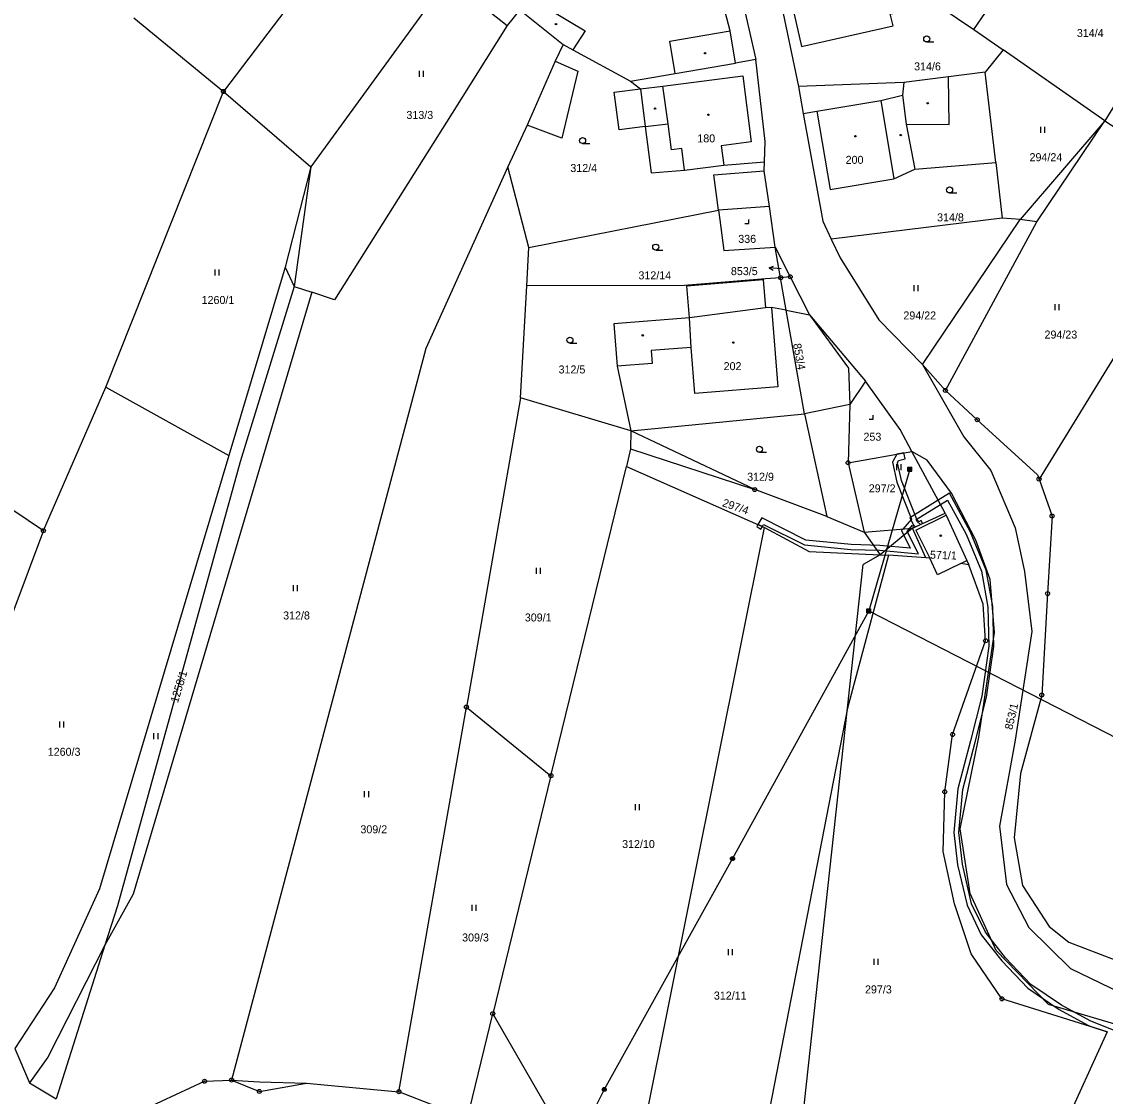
# Model space of a CAD drawing. Extents: x -745926 to -742978, y -968282 to -965689.
# Drawn here: x -745276.5 to -745141.1, y -967171.8 to -967037.5 of the extents above; entities that cross this region are included whole.
import ezdxf

# ---------------------------------------------------------------- set-up
doc = ezdxf.new("R2010")
doc.units = 0
for name, color, linetype in [('Hranice parcel', 7, 'Continuous'), ('Parcelní čísla', 7, 'Continuous'), ('Pop  PČ popisy', 7, 'Continuous'), ('Poz předměty', 7, 'Continuous'), ('Vnitřní kresba', 7, 'Continuous'), ('Věcná břemena k části', 7, 'Continuous'), ('Značky bodu BP', 7, 'Continuous'), ('Značky budov', 7, 'Continuous'), ('Značky kultur', 7, 'Continuous')]:
    doc.layers.add(name, color=color, linetype=linetype)

msp = doc.modelspace()

# ---------------------------------------------------------------- linework, layer by layer
at = {"layer": 'Hranice parcel'}
for p, q in [((-745131.16, -967033.55), (-745141.13, -967049.86)), ((-745161.57, -967035.67), (-745157.47, -967038.45)), ((-745262.49, -967036.98), (-745251.29, -967046.18)), ((-745214.25, -967035.97), (-745208.81, -967040.3)), ((-745157.47, -967038.45), (-745153.8, -967040.96)), ((-745153.8, -967040.96), (-745156.06, -967043.77)), ((-745141.13, -967049.86), (-745153.8, -967040.96)), ((-745184.74, -967042.18), (-745187.27, -967042.62)), ((-745154.74, -967055.05), (-745156.06, -967043.77)), ((-745265.99, -967083.14), (-745251.29, -967046.18)), ((-745251.29, -967046.18), (-745240.35, -967055.61)), ((-745179.42, -967045.57), (-745178.81, -967048.94)), ((-745141.13, -967049.86), (-745151.7, -967062.16)), ((-745240.35, -967055.61), (-745243.55, -967068.15)), ((-745213.09, -967065.69), (-745215.73, -967055.61)), ((-745154.74, -967055.05), (-745153.93, -967062.02)), ((-745213.09, -967065.69), (-745189.4, -967061.03)), ((-745183.02, -967060.56), (-745189.4, -967061.03)), ((-745182.31, -967065.65), (-745183.02, -967060.56)), ((-745153.93, -967062.02), (-745175.32, -967064.62)), ((-745163.92, -967080.29), (-745151.7, -967062.16)), ((-745151.7, -967062.16), (-745153.93, -967062.02)), ((-745130.76, -967064.38), (-745149.34, -967094.62)), ((-745213.36, -967070.48), (-745213.09, -967065.69)), ((-745182.31, -967065.65), (-745180.44, -967069.34)), ((-745181.64, -967069.45), (-745182.31, -967065.65)), ((-745243.55, -967068.15), (-745250.59, -967091.69)), ((-745180.44, -967069.34), (-745181.64, -967069.45)), ((-745180.93, -967073.53), (-745181.64, -967069.45)), ((-745214.13, -967084.45), (-745213.36, -967070.48)), ((-745317.4, -967071.42), (-745273.79, -967101.07)), ((-745178.66, -967086.47), (-745180.93, -967073.53)), ((-745273.79, -967101.07), (-745265.99, -967083.14)), ((-745265.99, -967083.14), (-745250.59, -967091.69)), ((-745171.03, -967082.4), (-745173, -967085.3)), ((-745214.13, -967084.45), (-745220.91, -967123.12)), ((-745200.36, -967088.61), (-745214.13, -967084.45)), ((-745173, -967085.3), (-745178.66, -967086.47)), ((-745173, -967085.3), (-745173.2, -967092.59)), ((-745200.36, -967088.61), (-745178.66, -967086.47)), ((-745178.66, -967086.47), (-745175.87, -967099.31)), ((-745173.2, -967092.59), (-745165.25, -967091.18)), ((-745161.08, -967098.89), (-745165.25, -967091.18)), ((-745210.34, -967131.7), (-745200.89, -967093.07)), ((-745200.89, -967093.07), (-745183.65, -967100.66)), ((-745175.87, -967099.31), (-745171.18, -967101.25)), ((-745165.17, -967100.77), (-745161.08, -967098.89)), ((-745202.34, -967193.92), (-745183.65, -967100.66)), ((-745171.18, -967101.25), (-745165.17, -967100.77)), ((-745163.47, -967104.47), (-745165.17, -967100.77)), ((-745273.79, -967101.07), (-745289.83, -967143.94)), ((-745163.47, -967104.47), (-745168.16, -967104.13)), ((-745158.35, -967104.82), (-745158.1, -967105.36)), ((-745229.35, -967171.2), (-745220.91, -967123.12)), ((-745220.91, -967123.12), (-745210.34, -967131.7)), ((-745210.34, -967131.7), (-745217.61, -967161.45)), ((-745266.1, -967152.9), (-745273.25, -967166.88)), ((-745221.16, -967175.97), (-745217.61, -967161.45)), ((-745277.35, -967165.81), (-745275.54, -967170.09)), ((-745273.25, -967166.88), (-745275.54, -967170.09)), ((-745275.54, -967170.09), (-745272.2, -967172.1))]:
    msp.add_line(p, q, dxfattribs=at)
for points in [[(-745221.16, -967004.14), (-745225.97, -967012.23), (-745227.76, -967015.24), (-745251.29, -967046.18)], [(-745157.47, -967038.45), (-745155.56, -967035.64), (-745148.37, -967021.19), (-745150.01, -967017.97)], [(-745213.9, -967019.17), (-745216.8, -967023.23), (-745240.35, -967055.61)], [(-745189.08, -967024.61), (-745186.49, -967034.46), (-745184.74, -967042.18)], [(-745187.27, -967042.62), (-745187.96, -967038.61), (-745188.97, -967034.61), (-745190.87, -967026.9)], [(-745182.66, -967029.42), (-745181.59, -967029.18), (-745181.27, -967030.59), (-745179.03, -967040.55), (-745167.58, -967037.97), (-745167.93, -967036.46), (-745161.57, -967035.67)], [(-745182.66, -967029.42), (-745181.69, -967034.61), (-745179.42, -967045.57)], [(-745214.25, -967035.97), (-745215.81, -967037.95), (-745222.69, -967048.89), (-745237.4, -967072.23), (-745240.22, -967071.25)], [(-745208.81, -967040.3), (-745209.8, -967042.4), (-745213.3, -967050.4), (-745215.73, -967055.61)], [(-745208.81, -967040.3), (-745207.59, -967040.96), (-745200.38, -967044.87)], [(-745183.65, -967054.95), (-745183.55, -967052.43), (-745184.74, -967042.18)], [(-745200.38, -967044.87), (-745194.81, -967043.91), (-745187.27, -967042.62)], [(-745156.06, -967043.77), (-745160.67, -967044.36), (-745166.24, -967045.05), (-745179.42, -967045.57)], [(-745200.38, -967044.87), (-745199.17, -967045.86), (-745198.57, -967050.57), (-745197.83, -967056.36), (-745193.65, -967056.02), (-745188.75, -967055.38), (-745183.65, -967054.95)], [(-745178.81, -967048.94), (-745177.11, -967048.64), (-745175.46, -967058.44), (-745167.48, -967057.1), (-745164.85, -967055.87), (-745154.74, -967055.05)], [(-745178.81, -967048.94), (-745176.36, -967062.39), (-745175.32, -967064.62)], [(-745141.13, -967049.86), (-745131.6, -967056), (-745130.2, -967056.6), (-745127.59, -967058.73)], [(-745215.73, -967055.61), (-745226, -967078.32), (-745250.27, -967169.74)], [(-745183.02, -967060.56), (-745183.7, -967056.11), (-745183.65, -967054.95)], [(-745189.4, -967061.03), (-745189.24, -967062.22), (-745188.74, -967066.04), (-745182.31, -967065.65)], [(-745175.32, -967064.62), (-745174.21, -967066.97), (-745169.34, -967074.73), (-745163.92, -967080.29)], [(-745243.55, -967068.15), (-745242.42, -967070.54), (-745240.22, -967071.25)], [(-745181.64, -967069.45), (-745183.53, -967069.59), (-745193.67, -967070.41), (-745213.36, -967070.48)], [(-745180.44, -967069.34), (-745178.03, -967074.1), (-745171.03, -967082.4)], [(-745240.22, -967071.25), (-745262.57, -967146.49), (-745266.1, -967152.9)], [(-745180.93, -967073.53), (-745182.77, -967073.17), (-745183.52, -967073.23), (-745193.04, -967074.45), (-745202.5, -967075.21), (-745202.07, -967080.53), (-745200.36, -967088.61)], [(-745163.92, -967080.29), (-745161.04, -967083.55), (-745157.06, -967087.21), (-745149.52, -967094.1), (-745149.34, -967094.62)], [(-745165.25, -967091.18), (-745166.68, -967088.44), (-745171.03, -967082.4)], [(-745200.36, -967088.61), (-745200.39, -967090.85), (-745200.89, -967093.07)], [(-745175.87, -967099.31), (-745184.88, -967095.93), (-745200.36, -967088.61)], [(-745250.59, -967091.69), (-745266.78, -967145.82), (-745272.38, -967158.2), (-745277.35, -967165.81)], [(-745149.34, -967094.62), (-745147.71, -967099.24), (-745148.26, -967108.93), (-745148.99, -967121.62), (-745151.66, -967131.42), (-745152.45, -967139.46), (-745151.39, -967145.42), (-745148.07, -967150.56), (-745145.63, -967152.52), (-745139.72, -967154.74)], [(-745161.08, -967098.89), (-745160.96, -967099.14), (-745158.35, -967104.82)], [(-745183.65, -967100.66), (-745178.07, -967103.66), (-745169.2, -967104.1), (-745168.16, -967104.13)], [(-745168.16, -967104.13), (-745173.28, -967123.27), (-745188.63, -967202.08)], [(-745158.1, -967105.36), (-745159.1, -967105.18), (-745162.03, -967106.6), (-745163, -967104.5), (-745163.47, -967104.47)], [(-745140.8, -967163.7), (-745153.98, -967159.59), (-745157.83, -967153.98), (-745159.91, -967147.72), (-745161.3, -967141.18), (-745161.12, -967133.71), (-745160.15, -967126.55), (-745156.01, -967114.84), (-745156.32, -967110.25), (-745158.1, -967105.36)], [(-745217.61, -967161.45), (-745208.73, -967176.85), (-745209.67, -967186.88)], [(-745140.8, -967163.7), (-745146.38, -967175.86), (-745148.19, -967179.8), (-745158.64, -967202.56)], [(-745263.16, -967178.41), (-745260.83, -967173.2), (-745253.64, -967169.89), (-745250.27, -967169.74)], [(-745250.27, -967169.74), (-745246.79, -967171.17), (-745240.91, -967170.14), (-745229.35, -967171.2)], [(-745221.16, -967175.97), (-745224.66, -967173.06), (-745229.35, -967171.2)]]:
    msp.add_lwpolyline(points, dxfattribs=at)
at = {"layer": 'Pop  PČ popisy'}
for p, q in [((-745183.06, -967068.23), (-745182.54, -967068.01)), ((-745181.56, -967068.33), (-745183.06, -967068.23)), ((-745183.06, -967068.23), (-745182.58, -967068.51))]:
    msp.add_line(p, q, dxfattribs=at)
at = {"layer": 'Poz předměty'}
for p, q in [((-745165.47, -967093.4), (-745170.61, -967111.1)), ((-745165.72, -967093.15), (-745165.22, -967093.15)), ((-745165.72, -967093.65), (-745165.72, -967093.15)), ((-745165.72, -967093.25), (-745165.22, -967093.25)), ((-745165.72, -967093.35), (-745165.22, -967093.35)), ((-745165.72, -967093.45), (-745165.22, -967093.45)), ((-745165.72, -967093.55), (-745165.22, -967093.55)), ((-745165.72, -967093.65), (-745165.22, -967093.65)), ((-745165.62, -967093.65), (-745165.62, -967093.15)), ((-745165.52, -967093.65), (-745165.52, -967093.15)), ((-745165.42, -967093.65), (-745165.42, -967093.15)), ((-745165.32, -967093.65), (-745165.32, -967093.15)), ((-745165.22, -967093.65), (-745165.22, -967093.15)), ((-745170.61, -967111.1), (-745187.65, -967142.06)), ((-745170.86, -967110.85), (-745170.36, -967110.85)), ((-745170.86, -967111.35), (-745170.86, -967110.85)), ((-745170.86, -967110.95), (-745170.36, -967110.95)), ((-745170.86, -967111.05), (-745170.36, -967111.05)), ((-745170.86, -967111.15), (-745170.36, -967111.15)), ((-745170.86, -967111.25), (-745170.36, -967111.25)), ((-745170.86, -967111.35), (-745170.36, -967111.35)), ((-745170.76, -967111.35), (-745170.76, -967110.85)), ((-745170.66, -967111.35), (-745170.66, -967110.85)), ((-745170.61, -967111.1), (-745093.52, -967150.64)), ((-745170.56, -967111.35), (-745170.56, -967110.85)), ((-745170.46, -967111.35), (-745170.46, -967110.85)), ((-745170.36, -967111.35), (-745170.36, -967110.85)), ((-745187.65, -967142.06), (-745203.68, -967170.92)), ((-745203.68, -967170.92), (-745225.94, -967214.52))]:
    msp.add_line(p, q, dxfattribs=at)
for centre, radius in [((-745187.65, -967142.06), 0.25), ((-745187.65, -967142.06), 0.2), ((-745187.65, -967142.06), 0.15), ((-745187.65, -967142.06), 0.1), ((-745187.65, -967142.06), 0.05), ((-745203.68, -967170.92), 0.25), ((-745203.68, -967170.92), 0.2), ((-745203.68, -967170.92), 0.15), ((-745203.68, -967170.92), 0.1), ((-745203.68, -967170.92), 0.05)]:
    msp.add_circle(centre, radius, dxfattribs=at)
at = {"layer": 'Vnitřní kresba'}
for p, q in [((-745213, -967034.43), (-745206.07, -967038.58)), ((-745218.56, -967035.78), (-745215.81, -967037.95)), ((-745206.07, -967038.58), (-745207.59, -967040.96)), ((-745195.5, -967039.89), (-745187.96, -967038.61)), ((-745194.81, -967043.91), (-745195.5, -967039.89)), ((-745209.8, -967042.4), (-745207, -967043.65)), ((-745207, -967043.65), (-745209, -967052)), ((-745196.34, -967045.5), (-745186.38, -967044.2)), ((-745186.38, -967044.2), (-745185.3, -967052.48)), ((-745166.24, -967045.05), (-745166.42, -967046.64)), ((-745160.56, -967050.3), (-745160.67, -967044.36)), ((-745202.43, -967046.28), (-745199.17, -967045.86)), ((-745201.81, -967050.99), (-745202.43, -967046.28)), ((-745199.17, -967045.86), (-745196.34, -967045.5)), ((-745195.7, -967050.2), (-745196.34, -967045.5)), ((-745177.11, -967048.64), (-745169.13, -967047.3)), ((-745169.13, -967047.3), (-745166.42, -967046.64)), ((-745169.13, -967047.3), (-745167.48, -967057.1)), ((-745166.42, -967046.64), (-745165.93, -967050.27)), ((-745209, -967052), (-745213.3, -967050.4)), ((-745198.57, -967050.57), (-745201.81, -967050.99)), ((-745198.57, -967050.57), (-745195.7, -967050.2)), ((-745195.28, -967053.48), (-745195.7, -967050.2)), ((-745165.93, -967050.27), (-745164.85, -967055.87)), ((-745165.93, -967050.27), (-745160.56, -967050.3)), ((-745149.63, -967062.45), (-745141.13, -967049.86)), ((-745194, -967053.31), (-745195.28, -967053.48)), ((-745193.65, -967056.02), (-745194, -967053.31)), ((-745185.3, -967052.48), (-745189.06, -967052.97)), ((-745189.06, -967052.97), (-745188.75, -967055.38)), ((-745240.35, -967055.61), (-745242.42, -967070.54)), ((-745189.98, -967056.59), (-745183.7, -967056.11)), ((-745189.4, -967061.03), (-745189.98, -967056.59)), ((-745161.04, -967083.55), (-745149.63, -967062.45)), ((-745149.63, -967062.45), (-745151.7, -967062.16)), ((-745242.42, -967070.54), (-745249.19, -967092.46)), ((-745193.36, -967070.46), (-745183.81, -967069.69)), ((-745193.04, -967074.45), (-745193.36, -967070.46)), ((-745183.81, -967069.69), (-745183.52, -967073.23)), ((-745182.77, -967073.17), (-745181.98, -967083.11)), ((-745180.93, -967073.53), (-745178.03, -967074.1)), ((-745192.82, -967078.16), (-745193.04, -967074.45)), ((-745178.03, -967074.1), (-745173.16, -967080.74)), ((-745192.82, -967078.16), (-745197.83, -967078.56)), ((-745197.83, -967078.56), (-745197.7, -967080.18)), ((-745192.36, -967083.94), (-745192.82, -967078.16)), ((-745197.7, -967080.18), (-745202.07, -967080.53)), ((-745163.92, -967080.29), (-745158.72, -967089.35)), ((-745173.16, -967080.74), (-745173, -967085.3)), ((-745181.98, -967083.11), (-745192.36, -967083.94)), ((-745158.72, -967089.35), (-745155.38, -967093.57)), ((-745200.39, -967090.85), (-745184.88, -967095.93)), ((-745163.32, -967092.26), (-745165.25, -967091.18)), ((-745249.19, -967092.46), (-745264.51, -967147.97)), ((-745173.2, -967092.59), (-745171.18, -967101.25)), ((-745160.29, -967096.38), (-745163.32, -967092.26)), ((-745155.38, -967093.57), (-745152.31, -967100.73)), ((-745157.22, -967102.27), (-745160.29, -967096.38)), ((-745164.75, -967100.99), (-745160.96, -967099.14)), ((-745165.17, -967100.77), (-745169.2, -967104.1)), ((-745152.31, -967100.73), (-745151.14, -967106.18)), ((-745171.18, -967101.25), (-745169.2, -967104.1)), ((-745164.75, -967100.99), (-745163, -967104.5)), ((-745155.45, -967107.19), (-745157.22, -967102.27)), ((-745169.2, -967104.1), (-745171.32, -967105.29)), ((-745159.1, -967105.18), (-745158.35, -967104.82)), ((-745173.28, -967123.27), (-745171.32, -967105.29)), ((-745151.14, -967106.18), (-745150.25, -967113.69)), ((-745154.91, -967113.79), (-745155.45, -967107.19)), ((-745156.86, -967126.88), (-745154.91, -967113.79)), ((-745150.25, -967113.69), (-745152.32, -967127.25)), ((-745181.92, -967202.47), (-745173.28, -967123.27)), ((-745159.2, -967138.35), (-745156.86, -967126.88)), ((-745152.32, -967127.25), (-745154.29, -967138.02)), ((-745157.95, -967146.44), (-745159.2, -967138.35)), ((-745154.29, -967138.02), (-745153.39, -967145.29)), ((-745153.39, -967145.29), (-745150.6, -967150.68)), ((-745154.71, -967153.54), (-745157.95, -967146.44)), ((-745264.51, -967147.97), (-745266.1, -967152.9)), ((-745150.6, -967150.68), (-745145.4, -967155.81)), ((-745266.1, -967152.9), (-745272.2, -967172.1)), ((-745148.17, -967160.28), (-745154.71, -967153.54)), ((-745145.4, -967155.81), (-745137.7, -967159.51)), ((-745139.59, -967162.84), (-745148.17, -967160.28)), ((-745250.27, -967169.74), (-745246.79, -967169.97)), ((-745246.79, -967169.97), (-745240.91, -967170.14))]:
    msp.add_line(p, q, dxfattribs=at)
at = {"layer": 'Věcná břemena k části'}
for points in [[(-745167.65, -967092.52), (-745167.11, -967095), (-745165.28, -967099.63), (-745166.37, -967100.87), (-745166.54, -967101.06), (-745165.43, -967103.26), (-745169.25, -967102.91), (-745172.8, -967102.81), (-745178.5, -967102.27), (-745184, -967099.48), (-745184.47, -967100.3), (-745183.91, -967100.54), (-745183.76, -967100.28), (-745178.66, -967102.85), (-745172.84, -967103.41), (-745169.29, -967103.51), (-745164.41, -967103.96), (-745165.82, -967101.16), (-745165.15, -967100.37), (-745165.02, -967100.7), (-745163.91, -967100.19), (-745164.06, -967099.81), (-745164.38, -967099.97), (-745164.66, -967099.55), (-745166.53, -967094.82), (-745167.01, -967092.6), (-745166.92, -967092.31), (-745166.07, -967092.1), (-745166.24, -967091.36), (-745167.11, -967091.51)], [(-745183.91, -967100.54), (-745184.47, -967100.3), (-745184.62, -967100.57), (-745184.1, -967100.87)]]:
    msp.add_lwpolyline(points, close=True, dxfattribs=at)
for points in [[(-745155.13, -967110.56), (-745155.96, -967105.99), (-745157.9, -967101.26), (-745160.54, -967096.4), (-745161.95, -967097.27), (-745165.48, -967099.45), (-745165.02, -967100.35), (-745164.76, -967100.58), (-745164.16, -967100.31), (-745164.54, -967099.97), (-745164.7, -967099.67), (-745161.67, -967097.8), (-745160.76, -967097.24), (-745158.44, -967101.52), (-745156.54, -967106.15), (-745155.73, -967110.62), (-745155.6, -967115.51), (-745156.48, -967121.77), (-745157.89, -967127.35), (-745159.47, -967133.34), (-745159.97, -967138.8), (-745159.51, -967142.86), (-745158.32, -967147.9), (-745156.56, -967151.58), (-745153.98, -967154.86), (-745150.75, -967158.27), (-745146.84, -967160.92), (-745143.22, -967162.89), (-745142.6, -967163.14), (-745140.8, -967163.7)], [(-745139.3, -967163.81), (-745142.96, -967162.35), (-745146.52, -967160.4), (-745150.35, -967157.81), (-745153.52, -967154.46), (-745156.04, -967151.26), (-745157.76, -967147.7), (-745158.91, -967142.76), (-745159.37, -967138.8), (-745158.87, -967133.44), (-745157.31, -967127.49), (-745155.9, -967121.89), (-745155, -967115.55), (-745155.13, -967110.56)]]:
    msp.add_lwpolyline(points, dxfattribs=at)
at = {"layer": 'Značky bodu BP'}
for centre, radius in [((-745251.29, -967046.18), 0.25), ((-745251.29, -967046.18), 0.0152), ((-745181.64, -967069.45), 0.25), ((-745181.64, -967069.45), 0.0152), ((-745180.44, -967069.34), 0.25), ((-745180.44, -967069.34), 0.0152), ((-745161.04, -967083.55), 0.25), ((-745161.04, -967083.55), 0.0152), ((-745157.06, -967087.21), 0.25), ((-745157.06, -967087.21), 0.0152), ((-745173.2, -967092.59), 0.25), ((-745173.2, -967092.59), 0.0152), ((-745149.34, -967094.62), 0.25), ((-745149.34, -967094.62), 0.0152), ((-745184.88, -967095.93), 0.25), ((-745184.88, -967095.93), 0.0152), ((-745147.71, -967099.24), 0.25), ((-745147.71, -967099.24), 0.0152), ((-745273.79, -967101.07), 0.25), ((-745273.79, -967101.07), 0.0152), ((-745148.26, -967108.93), 0.25), ((-745148.26, -967108.93), 0.0152), ((-745156.01, -967114.84), 0.25), ((-745156.01, -967114.84), 0.0152), ((-745148.99, -967121.62), 0.25), ((-745148.99, -967121.62), 0.0152), ((-745220.91, -967123.12), 0.25), ((-745220.91, -967123.12), 0.0152), ((-745160.15, -967126.55), 0.25), ((-745160.15, -967126.55), 0.0152), ((-745210.34, -967131.7), 0.25), ((-745210.34, -967131.7), 0.0152), ((-745161.12, -967133.71), 0.25), ((-745161.12, -967133.71), 0.0152), ((-745153.98, -967159.59), 0.25), ((-745153.98, -967159.59), 0.0152), ((-745217.61, -967161.45), 0.25), ((-745217.61, -967161.45), 0.0152), ((-745253.64, -967169.89), 0.25), ((-745253.64, -967169.89), 0.0152), ((-745250.27, -967169.74), 0.25), ((-745250.27, -967169.74), 0.0152), ((-745246.79, -967171.17), 0.25), ((-745246.79, -967171.17), 0.0152), ((-745229.35, -967171.2), 0.25), ((-745229.35, -967171.2), 0.0152)]:
    msp.add_circle(centre, radius, dxfattribs=at)
at = {"layer": 'Značky budov'}
for centre in [(-745209.71, -967037.76), (-745191.08, -967041.4), (-745163.24, -967047.64), (-745197.33, -967048.31), (-745190.66, -967049.09), (-745172.29, -967051.77), (-745166.62, -967051.63), (-745198.87, -967076.66), (-745187.56, -967077.56), (-745161.62, -967101.7)]:
    msp.add_circle(centre, 0.0875, dxfattribs=at)
at = {"layer": 'Značky kultur'}
for p, q in [((-745163.38, -967039.99), (-745162.5, -967039.99)), ((-745226.79, -967044.34), (-745226.79, -967043.59)), ((-745226.29, -967044.34), (-745226.29, -967043.59)), ((-745149.13, -967051.34), (-745149.13, -967050.59)), ((-745148.62, -967051.34), (-745148.62, -967050.59)), ((-745206.38, -967052.69), (-745205.5, -967052.69)), ((-745160.51, -967058.86), (-745159.63, -967058.86)), ((-745186.1, -967062.68), (-745185.6, -967062.68)), ((-745185.6, -967062.68), (-745185.6, -967062.18)), ((-745197.25, -967066.01), (-745196.37, -967066.01)), ((-745252.32, -967069.19), (-745252.32, -967068.44)), ((-745251.82, -967069.19), (-745251.82, -967068.44)), ((-745164.93, -967071.12), (-745164.93, -967070.37)), ((-745164.43, -967071.12), (-745164.43, -967070.37)), ((-745147.3, -967073.51), (-745147.3, -967072.76)), ((-745146.8, -967073.51), (-745146.8, -967072.76)), ((-745207.97, -967077.64), (-745207.09, -967077.64)), ((-745170.57, -967087.12), (-745170.07, -967087.12)), ((-745170.07, -967087.12), (-745170.07, -967086.62)), ((-745184.28, -967091.28), (-745183.4, -967091.28)), ((-745167.09, -967093.49), (-745167.09, -967092.74)), ((-745166.58, -967093.49), (-745166.58, -967092.74)), ((-745212.17, -967106.45), (-745212.17, -967105.7)), ((-745211.67, -967106.45), (-745211.67, -967105.7)), ((-745242.54, -967108.62), (-745242.54, -967107.87)), ((-745242.04, -967108.62), (-745242.04, -967107.87)), ((-745271.73, -967125.66), (-745271.73, -967124.91)), ((-745271.22, -967125.66), (-745271.22, -967124.91)), ((-745259.96, -967127.13), (-745259.96, -967126.38)), ((-745259.45, -967127.13), (-745259.45, -967126.38)), ((-745233.63, -967134.39), (-745233.63, -967133.64)), ((-745233.12, -967134.39), (-745233.12, -967133.64)), ((-745199.79, -967135.99), (-745199.79, -967135.24)), ((-745199.29, -967135.99), (-745199.29, -967135.24)), ((-745220.19, -967148.58), (-745220.19, -967147.83)), ((-745219.69, -967148.58), (-745219.69, -967147.83)), ((-745188.16, -967154.13), (-745188.16, -967153.38)), ((-745187.66, -967154.13), (-745187.66, -967153.38)), ((-745169.94, -967155.36), (-745169.94, -967154.61)), ((-745169.44, -967155.36), (-745169.44, -967154.61))]:
    msp.add_line(p, q, dxfattribs=at)
for centre in [(-745163.38, -967039.61), (-745206.38, -967052.31), (-745160.51, -967058.48), (-745197.25, -967065.63), (-745207.97, -967077.26), (-745184.28, -967090.9)]:
    msp.add_circle(centre, 0.375, dxfattribs=at)

# ---------------------------------------------------------------- texts
at = {"layer": 'Parcelní čísla'}
for s, p in [('314/4', (-745144.61, -967039.37)), ('314/6', (-745164.95, -967043.54)), ('313/3', (-745228.41, -967049.61)), ('180', (-745192.05, -967052.54)), ('200', (-745173.51, -967055.22)), ('294/24', (-745150.52, -967054.89)), ('312/4', (-745207.92, -967056.24)), ('314/8', (-745162.08, -967062.41)), ('336', (-745186.93, -967065.1)), ('853/5', (-745187.85, -967069.13)), ('312/14', (-745199.41, -967069.66)), ('1260/1', (-745254.01, -967072.74)), ('294/22', (-745166.29, -967074.67)), ('294/23', (-745148.65, -967077.06)), ('312/5', (-745209.39, -967081.42)), ('202', (-745188.76, -967081.01)), ('253', (-745171.28, -967089.83)), ('312/9', (-745185.82, -967094.83)), ('297/2', (-745170.62, -967096.28)), ('312/8', (-745243.82, -967112.17)), ('309/1', (-745213.61, -967112.42)), ('1260/3', (-745273.24, -967129.21)), ('309/2', (-745234.16, -967138.9)), ('312/10', (-745201.45, -967140.74)), ('309/3', (-745221.45, -967152.42)), ('312/11', (-745189.98, -967159.68)), ('297/3', (-745171.09, -967158.91))]:
    msp.add_text(s, height=1, dxfattribs=at).set_placement(p)
for s, rotation, p in [('853/4', 280, (-745180.08, -967077.75)), ('297/4', 341, (-745189, -967097.99)), ('571/1', 358, (-745162.98, -967104.57)), ('1258/1', 73, (-745256.97, -967122.66)), ('853/1', 77, (-745152.68, -967126.03))]:
    msp.add_text(s, height=1, rotation=rotation, dxfattribs=at).set_placement(p)

doc.saveas('drawing.dxf')
